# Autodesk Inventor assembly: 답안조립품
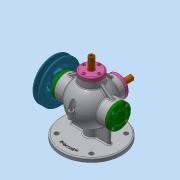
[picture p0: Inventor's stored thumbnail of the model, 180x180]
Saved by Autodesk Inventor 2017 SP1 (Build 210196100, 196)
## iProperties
Part Number: 답안조립품
Material: 일반
Document SubType Name: Assembly
Designer: MRC
Author: MRC
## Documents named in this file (17)
- C:\Users\MRC\Desktop\620909V1003\답안조립품.iam
- C:\Users\MRC\Desktop\620909V1003\본체.ipt
- C:\Users\MRC\Desktop\620909V1003\V-벨트풀리.ipt
- C:\Users\MRC\Desktop\620909V1003\너트-M8x1.ipt
- C:\Users\MRC\Desktop\620909V1003\뒤커버.ipt
- C:\Users\MRC\Desktop\620909V1003\베어링- 6202.ipt
- C:\Users\MRC\Desktop\620909V1003\본체커버.ipt
- C:\Users\MRC\Desktop\620909V1003\볼트 M4x0.7.ipt
- C:\Users\MRC\Desktop\620909V1003\슬라이드 커버.ipt
- C:\Users\MRC\Desktop\620909V1003\슬라이드.ipt
- C:\Users\MRC\Desktop\620909V1003\앞커버.ipt
- C:\Users\MRC\Desktop\620909V1003\오일실.ipt
- C:\Users\MRC\Desktop\620909V1003\와셔 8x17.ipt
- C:\Users\MRC\Desktop\620909V1003\축.ipt
- C:\Users\MRC\Desktop\620909V1003\키-4x4.ipt
- C:\Users\MRC\Desktop\620909V1003\가변스프링1.ipt
- C:\Users\MRC\Desktop\620909V1003\가변스프링2.ipt
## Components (20 placed, 4 different names)
1. V-벨트풀리:1
2. 가변스프링1:1
3. 가변스프링2:1
4. M4x0.7x12:17
5. M4x0.7x12:2
6. M4x0.7x12:5
7. M4x0.7x12:6
8. M4x0.7x12:7
9. M4x0.7x12:4
10. M4x0.7x12:8
11. M4x0.7x12:9
12. M4x0.7x12:10
13. M4x0.7x12:1
14. M4x0.7x12:11
15. M4x0.7x12:12
16. M4x0.7x12:13
17. M4x0.7x12:3
18. M4x0.7x12:14
19. M4x0.7x12:15
20. M4x0.7x12:16
